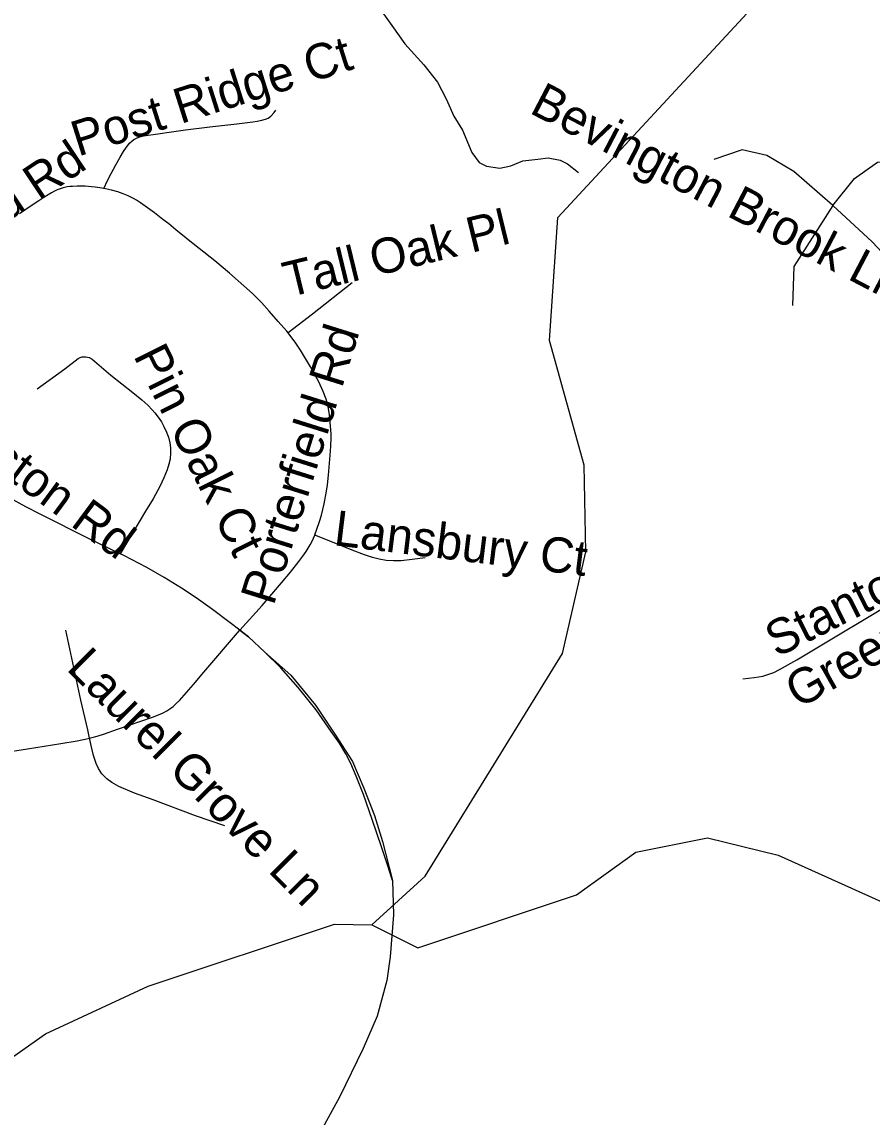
# Model space of a CAD drawing. Extents: x 1383679 to 1536984, y 460658 to 651027.
# Drawn here: x 1448318 to 1450610, y 486697 to 489649 of the extents above; entities that cross this region are included whole.
import ezdxf

# ---------------------------------------------------------------- set-up
doc = ezdxf.new("R2010")
doc.units = 0
for name, color, linetype in [('Exist Hydrographic Creek Single Shore', 7, 'Continuous'), ('Exist Hydrographic Misc Water Feature', 7, 'Continuous'), ('Exist Road Non-System Type 51', 7, 'Continuous'), ('Exist Road Non-System Type 51 Label', 7, 'Continuous')]:
    doc.layers.add(name, color=color, linetype=linetype)

msp = doc.modelspace()

# ---------------------------------------------------------------- linework, layer by layer
at = {"layer": 'Exist Hydrographic Creek Single Shore'}
for points in [[(1449261.2, 487215), (1449405.2, 487346.7), (1449775.3, 487946.5), (1449838.2, 488221), (1449834.2, 488454.1), (1449740.2, 488790.8), (1449763.3, 489121.8), (1450613.2, 490040.2), (1450887.3, 490435.1), (1451074.3, 490625.1), (1451375.5, 491065.7), (1451601.1, 491426.2), (1451635.8, 491480.8), (1451867.2, 492010.7), (1452203.3, 492621), (1452383.2, 492903), (1452603.2, 493098.8), (1453256.2, 493220.2)], [(1449261.2, 487215), (1449385.2, 487153.4), (1449813.2, 487295.9), (1449973.2, 487410.7), (1450166.2, 487449.5), (1450357.2, 487403), (1450762.3, 487220.9)], [(1445349.2, 484808.9), (1445503.2, 485022.5), (1445665.2, 485245.7), (1445759.2, 485329.2), (1445950.2, 485325.3), (1446033.2, 485290.8), (1446276.2, 485335.2), (1446897.2, 485565.6), (1446991.2, 485704.8), (1447022.2, 486039), (1447192.2, 486219.4), (1447546.2, 486438.7), (1448127.2, 486742.2), (1448381.2, 486920.9), (1448658.2, 487049.9), (1449161.2, 487217), (1449261.2, 487215)]]:
    msp.add_lwpolyline(points, dxfattribs=at)
at = {"layer": 'Exist Hydrographic Misc Water Feature'}
msp.add_lwpolyline([(1449284.1, 489683.5), (1449315.3, 489639.4), (1449350.5, 489590.3), (1449401.4, 489533.4), (1449438.6, 489486.7), (1449461.8, 489442), (1449482.9, 489395.6), (1449506.3, 489357.4), (1449531.2, 489297), (1449550.7, 489270.3), (1449570.6, 489260.1), (1449606.5, 489255.2), (1449636.6, 489261.2), (1449668.8, 489274.5), (1449709, 489279.4), (1449737, 489283), (1449768.9, 489276.6), (1449788.8, 489266.4), (1449818.4, 489243.6)], dxfattribs=at)
at = {"layer": 'Exist Road Non-System Type 51'}
for points in [[(1448539.3, 489200.6), (1448548.6, 489221.8), (1448558.3, 489240.2), (1448571.2, 489263.6), (1448583.1, 489284.8), (1448592, 489299.6), (1448599.9, 489311.4), (1448603.4, 489316), (1448608.4, 489322.1), (1448614.4, 489328), (1448620.2, 489332.1), (1448623.8, 489334.5), (1448628.5, 489337.1), (1448635.5, 489339.8), (1448645.9, 489342), (1448684.8, 489347.3), (1448721.2, 489353.3), (1448759.4, 489358.4), (1448825.1, 489366.2), (1448897.4, 489374.9), (1448940.2, 489380), (1448952.6, 489381.8), (1448965, 489384.1), (1448975.1, 489386.9), (1448982.1, 489390.1), (1448989.4, 489395.2), (1448998.6, 489404.8), (1449002.6, 489411.2)], [(1450712.7, 488439.6), (1450679.8, 488468.7), (1450650.6, 488512.5), (1450643.3, 488585.4), (1450672.5, 488673), (1450709, 488775.1), (1450716.3, 488848.1), (1450698, 488932), (1450665.2, 488997.6), (1450610.5, 489056), (1450504.8, 489154.5), (1450399.1, 489245.7), (1450326.2, 489289.5), (1450260.5, 489304.1), (1450184, 489278.5)], [(1450504.8, 489154.5), (1450563.1, 489227.5), (1450625.1, 489271.2), (1450709, 489278.5), (1450825.6, 489205.6), (1450956.9, 489088.8), (1451022.5, 489037.8), (1451113.6, 489015.9), (1451175.6, 489026.8), (1451229.2, 489055)], [(1449035.5, 488811.1), (1449031.9, 488815.7), (1449024.4, 488824.6), (1449009.3, 488842), (1448984.6, 488869.5), (1448963.6, 488893.2), (1448939.3, 488917.4), (1448916.7, 488938.1), (1448877.6, 488972), (1448837.8, 489004.8), (1448766.5, 489061.5), (1448760.9, 489066), (1448733.3, 489088.9), (1448713.8, 489105), (1448698.4, 489117), (1448675.5, 489134.6), (1448637.9, 489162), (1448626.6, 489169.2), (1448619, 489173.5), (1448604.3, 489180.4), (1448591.1, 489185.8), (1448576.3, 489190.8), (1448559.3, 489195.9), (1448543.2, 489199.6), (1448528, 489202.3), (1448515.7, 489203.8), (1448505.2, 489204.9), (1448497.3, 489205.4), (1448488.5, 489206.5), (1448477, 489206.5), (1448467.3, 489206.5), (1448454, 489206), (1448447.1, 489205.5), (1448439.7, 489204.6), (1448429.1, 489202.3), (1448418.5, 489198.6), (1448413, 489196.3), (1448405.6, 489192.7), (1448397.8, 489188.5), (1448388.6, 489183), (1448377.1, 489176.1), (1448363.3, 489167), (1448345.8, 489155.6), (1448311.8, 489131.9)], [(1450504.8, 489154.5), (1450399.1, 488990.3), (1450395.4, 488884.5)], [(1449208.9, 488946), (1449101.7, 488861.7), (1449035.5, 488811.1)], [(1449107.6, 488265.8), (1449108, 488266.8), (1449113.6, 488281.6), (1449120.3, 488302.7), (1449125.5, 488319.5), (1449132.8, 488350), (1449139.3, 488384.2), (1449141.7, 488401.5), (1449144.9, 488427.4), (1449150.5, 488492.1), (1449151.4, 488506.3), (1449152.1, 488527.5), (1449151.9, 488538.5), (1449150.3, 488559.7), (1449147.1, 488590.4), (1449143.5, 488612.9), (1449138.6, 488632), (1449130.7, 488653.2), (1449118.7, 488678.6), (1449096.4, 488719.5), (1449069.3, 488764.1), (1449054.6, 488785.5), (1449040.4, 488804.8), (1449035.5, 488811.1)], [(1448358.8, 488660.1), (1448434, 488714), (1448469.3, 488742.1), (1448474.9, 488744.8), (1448480.7, 488746.3), (1448489.9, 488746.8), (1448499.3, 488744.7), (1448507.1, 488740), (1448558.1, 488696.8), (1448617.3, 488649.9), (1448640.9, 488630.3), (1448657.2, 488616.2), (1448669.1, 488603.9), (1448676.5, 488595.6), (1448685.8, 488584), (1448694.2, 488570.7), (1448700.7, 488558.9), (1448708.1, 488543.4), (1448713.3, 488529.5), (1448716.9, 488514.2), (1448718.2, 488501.2), (1448718.7, 488488.7), (1448717.3, 488470.7), (1448714.1, 488456.8), (1448709.7, 488442), (1448700.9, 488419.8), (1448689.5, 488397.1), (1448672, 488364), (1448651.5, 488330.7), (1448583.2, 488215.1)], [(1448583.2, 488215.1), (1448501.5, 488254.4), (1448367, 488321.8), (1448328.6, 488342.1), (1448284.6, 488366.7), (1448248.7, 488388.7), (1448227.4, 488402.7)], [(1448905.3, 488009.3), (1448965.6, 488076.1), (1449017.9, 488136.8), (1449042.3, 488165.8), (1449065.1, 488194.2), (1449075.4, 488208.6), (1449084.4, 488221.3), (1449095.4, 488239.2), (1449100.4, 488249.7), (1449107.6, 488265.8)], [(1449405.1, 488204.1), (1449370, 488200.1), (1449340.4, 488196.8), (1449320.1, 488196.2), (1449299.8, 488197.5), (1449281.7, 488200.7), (1449263, 488205.4), (1449241.3, 488212.5), (1449208.2, 488225.2), (1449155.3, 488247.1), (1449107.6, 488265.8)], [(1448905.3, 488009.3), (1448879.9, 488029.1), (1448831.8, 488065), (1448787.4, 488096.7), (1448748.2, 488122.8), (1448701.5, 488151.2), (1448654.8, 488178.1), (1448592.8, 488210.5), (1448583.2, 488215.1)], [(1450262.3, 487878.1), (1450292.6, 487882.2), (1450315.6, 487885.9), (1450331.8, 487890.7), (1450345.1, 487895.6), (1450360.6, 487903), (1450407.9, 487929.8), (1450701.5, 488106)], [(1448500.3, 487718.5), (1448495.6, 487740.4), (1448477.3, 487821.2), (1448436.3, 488009.9)], [(1448500.3, 487718.5), (1448520.6, 487724), (1448541.1, 487730.4), (1448575.3, 487742.5), (1448670.3, 487774.5), (1448686.1, 487780.8), (1448698.7, 487786.5), (1448708.4, 487791.7), (1448716.9, 487797.3), (1448725.7, 487804.1), (1448734.3, 487811.5), (1448743.3, 487820.3), (1448780.8, 487863.3), (1448808.7, 487896.6), (1448904.3, 488008.2), (1448905.3, 488009.3)], [(1448905.2, 488009.3), (1448928.8, 487991.2), (1448973.2, 487949.8), (1449043.4, 487888.2), (1449109.8, 487807.2), (1449161.9, 487729), (1449209.8, 487655.1), (1449240.1, 487583.3), (1449268.4, 487509.5), (1449290.1, 487439.9), (1449316.9, 487334.2), (1449319.9, 487242.2), (1449311.1, 487128.7), (1449302.4, 487064.7), (1449276.2, 486968.6), (1449238.4, 486881.3), (1449174.4, 486750.3), (1448797.1, 486063), (1448693.4, 485857.5), (1448615.1, 485675.3)], [(1449316.9, 487334.2), (1449303.5, 487376.7), (1449288, 487425.1), (1449262.7, 487499), (1449238.7, 487566.1), (1449219.7, 487615.6), (1449204.6, 487650.2), (1449191.6, 487676.5), (1449174.6, 487704.5), (1449152.1, 487736), (1449111.6, 487795), (1449063.1, 487855.2), (1449016.2, 487907.6), (1448973.3, 487949.8), (1448928.7, 487991.1), (1448905.3, 488009.3)], [(1448126, 487657.7), (1448263.9, 487678.7), (1448332.8, 487689.3), (1448423.2, 487703.8), (1448466.7, 487711.4), (1448496.4, 487717.5), (1448500.3, 487718.5)], [(1448865.1, 487482.4), (1448785.7, 487508.6), (1448671.6, 487551.9), (1448621.6, 487570.4), (1448579, 487587.6), (1448560, 487598.7), (1448546.6, 487608.8), (1448533.7, 487622.3), (1448524.4, 487636.1), (1448517.9, 487650), (1448511, 487671.3), (1448507.2, 487686.7), (1448500.3, 487718.5)]]:
    msp.add_lwpolyline(points, dxfattribs=at)

# ---------------------------------------------------------------- texts
at = {"layer": 'Exist Road Non-System Type 51 Label'}
for s, rotation, p in [('Post Ridge Ct', 17.6301, (1448469.5, 489286)), ('Bevington Brook Ln', 332.439, (1449683.5, 489405.4)), ('Porterfield Rd', 33.6905, (1447851.8, 488825.6)), ('Tall Oak Pl', 13.6722, (1449035.7, 488906.3)), ('Porterfield Rd', 72.5843, (1448996.6, 488073.2)), ('Pin Oak Ct', 296.5419, (1448617.3, 488749.7)), ('Johnston Rd', 323.531, (1448002.9, 488620.3)), ('Lansbury Ct', 353.0198, (1449156.5, 488238.7)), ('Stanton', 26.5656, (1450353.1, 487934.7)), ('Green Ct', 29.4764, (1450412, 487796.3)), ('Laurel Grove Ln', 314.9567, (1448435.2, 487903.9))]:
    msp.add_text(s, height=95, rotation=rotation, dxfattribs=at).set_placement(p)

doc.saveas('drawing.dxf')
